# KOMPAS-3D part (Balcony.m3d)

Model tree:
1. Plane XY
2. Plane ZX
3. Plane ZY
4. X Axis
5. Y Axis
6. Z Axis
7. Origin

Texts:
  Steel DIN 17102
  Three Point Plane
  Plane at Angle
  Line and Point Plane
  Axis through Two Vertices
  Axis of Feature
  Axis of Conical Surface
  Axis through Edge
  Trim by Surface
  Trim by Sketch
  Feature with No History
  Intersection Axis of Two Planes
  Two Line Plane
  Line and Face Plane
  Bend by line
  Hole in sheet body
  Cut in sheet body
  Point in CM
  Linear Dimension from Line to Point
  Surface Finish Symbol
  Geometric Tolerance Symbol
  Leader #1
  Leader #2
  Leader #3
  Shape Deviations and Datum
  Node point number
  Mark of coordination axis
  Node point designation
  Mark/Reference designation with leader
  Mark/reference designation on line
  Mark/Reference designation without leader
